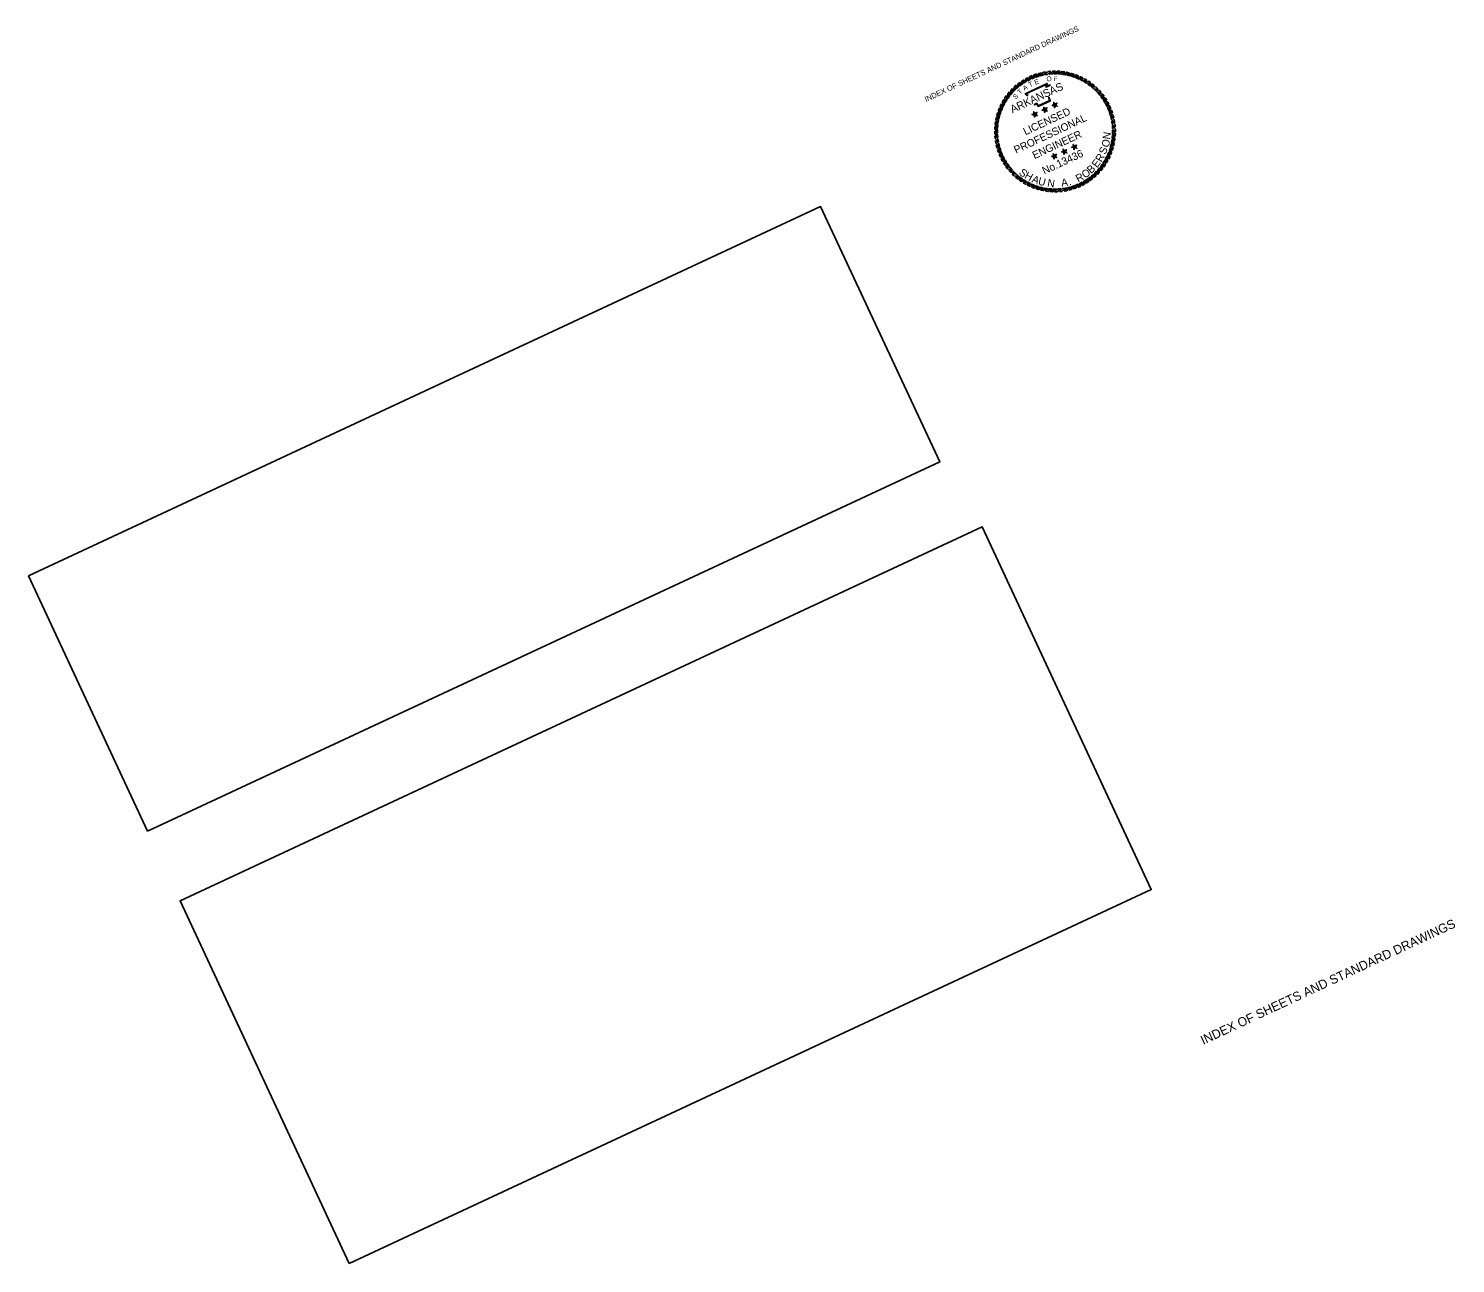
# Model space of a CAD drawing. Extents: x 757071 to 763666, y 1656563 to 1660766.
# Drawn here: x 757071 to 759892, y 1656563 to 1659005 of the extents above; entities that cross this region are included whole.
import ezdxf

# ---------------------------------------------------------------- set-up
doc = ezdxf.new("R2010")
doc.units = 0
for name, color, linetype in [('1', 7, 'Continuous'), ('60', 7, 'Continuous'), ('G-ANNO-SYMB', 7, 'Continuous')]:
    doc.layers.add(name, color=color, linetype=linetype)

msp = doc.modelspace()

# ---------------------------------------------------------------- linework, layer by layer
at = {"layer": '1'}
for points in [[(757306.4, 1657417.7), (758872.2, 1658147.8), (758636.7, 1658652.7), (757071, 1657922.6)], [(757704.8, 1656563.3), (759290.1, 1657302.5), (758955.7, 1658019.6), (757370.5, 1657280.3)]]:
    msp.add_lwpolyline(points, close=True, dxfattribs=at)
at = {"layer": 'G-ANNO-SYMB'}
for points in [[(759055.1, 1658911.6), (759050.4, 1658909.6), (759046.3, 1658901.5), (759051.2, 1658904)], [(759063.9, 1658914.8), (759059.1, 1658913.2), (759054.3, 1658905.4), (759059.4, 1658907.5)], [(759073, 1658917.3), (759068, 1658916), (759062.6, 1658908.7), (759067.9, 1658910.3)], [(759082.2, 1658919.1), (759077.1, 1658918.2), (759071.2, 1658911.3), (759076.6, 1658912.5)], [(759091.5, 1658920.1), (759086.4, 1658919.7), (759079.9, 1658913.2), (759085.4, 1658914)], [(759100.8, 1658920.4), (759095.7, 1658920.4), (759088.8, 1658914.4), (759094.3, 1658914.8)], [(759110.2, 1658920), (759105.1, 1658920.3), (759097.7, 1658915), (759103.2, 1658914.9)], [(759119.5, 1658918.9), (759114.4, 1658919.6), (759106.6, 1658914.8), (759112.2, 1658914.4)], [(759128.7, 1658917), (759123.7, 1658918.1), (759115.5, 1658913.9), (759121, 1658913.1)], [(759137.7, 1658914.4), (759132.8, 1658915.9), (759124.3, 1658912.4), (759129.7, 1658911.1)], [(759146.5, 1658911.1), (759141.7, 1658913), (759133, 1658910.1), (759138.2, 1658908.4)], [(759154.9, 1658907.1), (759150.3, 1658909.4), (759141.4, 1658907.2), (759146.5, 1658905.1)], [(759016.3, 1658886), (759012.7, 1658882.3), (759012, 1658873.2), (759015.6, 1658877.4)], [(759023.2, 1658892.3), (759019.3, 1658889), (759017.9, 1658879.9), (759021.8, 1658883.8)], [(759030.6, 1658898.1), (759026.5, 1658895), (759024.3, 1658886.1), (759028.6, 1658889.7)], [(759038.4, 1658903.3), (759034.1, 1658900.5), (759031.2, 1658891.8), (759035.7, 1658895.1)], [(759046.6, 1658907.8), (759042.1, 1658905.4), (759038.6, 1658896.9), (759043.3, 1658899.8)], [(759163.1, 1658902.5), (759158.7, 1658905.1), (759149.6, 1658903.6), (759154.6, 1658901.1)], [(759170.8, 1658897.2), (759166.6, 1658900.2), (759157.5, 1658899.4), (759162.2, 1658896.5)], [(759178.2, 1658891.4), (759174.2, 1658894.6), (759165.1, 1658894.6), (759169.5, 1658891.4)], [(759185, 1658885), (759181.3, 1658888.5), (759172.2, 1658889.3), (759176.4, 1658885.6)], [(759191.3, 1658878), (759187.9, 1658881.9), (759178.9, 1658883.3), (759182.8, 1658879.4)], [(758994.1, 1658856), (758991.9, 1658851.4), (758994, 1658842.5), (758996.1, 1658847.6)], [(758998.8, 1658864.1), (758996.1, 1658859.7), (758997.6, 1658850.7), (759000.1, 1658855.6)], [(759004, 1658871.9), (759001.1, 1658867.7), (759001.8, 1658858.6), (759004.7, 1658863.3)], [(759009.9, 1658879.2), (759006.6, 1658875.2), (759006.6, 1658866.1), (759009.9, 1658870.6)], [(759099.8, 1658853.4), (759098, 1658854.4), (759094.4, 1658852.7), (759098.3, 1658852)], [(759099.8, 1658853.4), (759100.2, 1658855.5), (759097.5, 1658858.4), (759098, 1658854.4)], [(759099.8, 1658853.4), (759098.3, 1658852), (759098.7, 1658848.1), (759100.7, 1658851.5)], [(759099.8, 1658853.4), (759101.9, 1658853.7), (759103.8, 1658857.1), (759100.2, 1658855.5)], [(759099.8, 1658853.4), (759100.7, 1658851.5), (759104.6, 1658850.8), (759101.9, 1658853.7)], [(759197.1, 1658870.6), (759194, 1658874.8), (759185.1, 1658876.9), (759188.7, 1658872.7)], [(759202.2, 1658862.8), (759199.5, 1658867.2), (759190.8, 1658870), (759194, 1658865.5)], [(759206.7, 1658854.6), (759204.3, 1658859.2), (759195.9, 1658862.7), (759198.8, 1658857.9)], [(759210.6, 1658846.1), (759208.6, 1658850.8), (759200.4, 1658855), (759202.9, 1658850)], [(758984.2, 1658829.7), (758983.1, 1658824.7), (758987.3, 1658816.6), (758988.2, 1658822)], [(758986.8, 1658838.7), (758985.3, 1658833.8), (758988.8, 1658825.4), (758990.1, 1658830.7)], [(758990.1, 1658847.5), (758988.3, 1658842.7), (758991.1, 1658834), (758992.8, 1658839.3)], [(759060.2, 1658835), (759058.4, 1658836), (759054.8, 1658834.3), (759058.7, 1658833.5)], [(759060.2, 1658835), (759060.6, 1658837), (759057.9, 1658839.9), (759058.4, 1658836)], [(759060.2, 1658835), (759058.7, 1658833.5), (759059.2, 1658829.6), (759061.1, 1658833.1)], [(759060.2, 1658835), (759062.3, 1658835.2), (759064.2, 1658838.7), (759060.6, 1658837)], [(759060.2, 1658835), (759061.1, 1658833.1), (759065, 1658832.3), (759062.3, 1658835.2)], [(759080, 1658844.2), (759078.2, 1658845.2), (759074.6, 1658843.5), (759078.5, 1658842.8)], [(759080, 1658844.2), (759080.4, 1658846.2), (759077.7, 1658849.1), (759078.2, 1658845.2)], [(759080, 1658844.2), (759078.5, 1658842.8), (759079, 1658838.8), (759080.9, 1658842.3)], [(759080, 1658844.2), (759082.1, 1658844.4), (759084, 1658847.9), (759080.4, 1658846.2)], [(759080, 1658844.2), (759080.9, 1658842.3), (759084.8, 1658841.5), (759082.1, 1658844.4)], [(759213.8, 1658837.3), (759212.1, 1658842.1), (759204.3, 1658846.9), (759206.5, 1658841.8)], [(759216.3, 1658828.2), (759215, 1658833.2), (759207.6, 1658838.6), (759209.3, 1658833.3)], [(759218.1, 1658819), (759217.2, 1658824.1), (759210.2, 1658830), (759211.5, 1658824.6)], [(758980.8, 1658801.9), (758980.9, 1658796.8), (758986.8, 1658789.8), (758986.4, 1658795.3)], [(758981.2, 1658811.2), (758980.9, 1658806.1), (758986.3, 1658798.7), (758986.3, 1658804.3)], [(758982.4, 1658820.5), (758981.6, 1658815.5), (758986.4, 1658807.7), (758986.9, 1658813.2)], [(759219.1, 1658809.7), (759218.6, 1658814.8), (759212.2, 1658821.3), (759213, 1658815.8)], [(759219.4, 1658800.4), (759219.3, 1658805.5), (759213.4, 1658812.5), (759213.8, 1658806.9)], [(759219, 1658791), (759219.3, 1658796.1), (759213.9, 1658803.5), (759213.9, 1658798)], [(758981.1, 1658792.5), (758981.6, 1658787.4), (758988, 1658780.9), (758987.2, 1658786.4)], [(758982.1, 1658783.2), (758983, 1658778.2), (758990, 1658772.2), (758988.7, 1658777.6)], [(758983.9, 1658774), (758985.2, 1658769), (758992.6, 1658763.7), (758990.9, 1658768.9)], [(759138.4, 1658770.6), (759136.6, 1658771.6), (759133, 1658769.9), (759136.9, 1658769.2)], [(759138.4, 1658770.6), (759138.8, 1658772.6), (759136.1, 1658775.5), (759136.6, 1658771.6)], [(759138.4, 1658770.6), (759136.9, 1658769.2), (759137.4, 1658765.3), (759139.3, 1658768.7)], [(759138.4, 1658770.6), (759140.5, 1658770.9), (759142.4, 1658774.3), (759138.8, 1658772.6)], [(759138.4, 1658770.6), (759139.3, 1658768.7), (759143.2, 1658768), (759140.5, 1658770.9)], [(759210, 1658754.8), (759211.9, 1658759.5), (759209.1, 1658768.2), (759207.4, 1658763)], [(759213.3, 1658763.5), (759214.8, 1658768.4), (759211.3, 1658776.9), (759210, 1658771.5)], [(759215.9, 1658772.5), (759217.1, 1658777.5), (759212.9, 1658785.7), (759212, 1658780.2)], [(759217.8, 1658781.7), (759218.5, 1658786.8), (759213.8, 1658794.6), (759213.3, 1658789.1)], [(758986.4, 1658765), (758988, 1658760.1), (758995.8, 1658755.3), (758993.7, 1658760.5)], [(758989.6, 1658756.2), (758991.6, 1658751.5), (758999.8, 1658747.3), (758997.3, 1658752.2)], [(758993.4, 1658747.6), (758995.8, 1658743.1), (759004.3, 1658739.6), (759001.4, 1658744.3)], [(759098.9, 1658752.2), (759097, 1658753.2), (759093.4, 1658751.5), (759097.3, 1658750.7)], [(759098.9, 1658752.2), (759099.2, 1658754.2), (759096.5, 1658757.1), (759097, 1658753.2)], [(759098.9, 1658752.2), (759097.3, 1658750.7), (759097.8, 1658746.8), (759099.7, 1658750.3)], [(759098.9, 1658752.2), (759100.9, 1658752.4), (759102.8, 1658755.9), (759099.2, 1658754.2)], [(759098.9, 1658752.2), (759099.7, 1658750.3), (759103.6, 1658749.5), (759100.9, 1658752.4)], [(759118.6, 1658761.4), (759116.8, 1658762.4), (759113.2, 1658760.7), (759117.1, 1658760)], [(759118.6, 1658761.4), (759119, 1658763.4), (759116.3, 1658766.3), (759116.8, 1658762.4)], [(759118.6, 1658761.4), (759117.1, 1658760), (759117.6, 1658756), (759119.5, 1658759.5)], [(759118.6, 1658761.4), (759120.7, 1658761.6), (759122.6, 1658765.1), (759119, 1658763.4)], [(759118.6, 1658761.4), (759119.5, 1658759.5), (759123.4, 1658758.7), (759120.7, 1658761.6)], [(759196.2, 1658730.4), (759199.1, 1658734.6), (759198.4, 1658743.7), (759195.5, 1658739)], [(759201.4, 1658738.1), (759204, 1658742.6), (759202.6, 1658751.6), (759200.1, 1658746.7)], [(759206.1, 1658746.3), (759208.3, 1658750.9), (759206.2, 1658759.8), (759204, 1658754.7)], [(758998, 1658739.4), (759000.7, 1658735.1), (759009.4, 1658732.3), (759006.2, 1658736.8)], [(759003.1, 1658731.6), (759006.2, 1658727.5), (759015.1, 1658725.4), (759011.5, 1658729.6)], [(759008.9, 1658724.2), (759012.3, 1658720.4), (759021.3, 1658718.9), (759017.4, 1658722.9)], [(759015.2, 1658717.3), (759018.9, 1658713.7), (759028, 1658713), (759023.8, 1658716.6)], [(759169.6, 1658704.2), (759173.7, 1658707.2), (759175.9, 1658716.1), (759171.6, 1658712.5)], [(759177, 1658709.9), (759180.9, 1658713.3), (759182.3, 1658722.3), (759178.4, 1658718.4)], [(759183.9, 1658716.2), (759187.5, 1658719.9), (759188.2, 1658729), (759184.6, 1658724.8)], [(759190.3, 1658723.1), (759193.6, 1658727), (759193.6, 1658736.2), (759190.3, 1658731.7)], [(759022, 1658710.9), (759026, 1658707.6), (759035.1, 1658707.6), (759030.7, 1658710.9)], [(759029.4, 1658705), (759033.5, 1658702.1), (759042.7, 1658702.8), (759037.9, 1658705.7)], [(759037.1, 1658699.8), (759041.5, 1658697.2), (759050.6, 1658698.6), (759045.6, 1658701.1)], [(759045.3, 1658695.2), (759049.9, 1658692.9), (759058.8, 1658695), (759053.6, 1658697.2)], [(759053.7, 1658691.2), (759058.5, 1658689.3), (759067.2, 1658692.1), (759061.9, 1658693.8)], [(759062.5, 1658687.9), (759067.4, 1658686.4), (759075.9, 1658689.9), (759070.5, 1658691.2)], [(759071.5, 1658685.3), (759076.5, 1658684.2), (759084.7, 1658688.3), (759079.2, 1658689.2)], [(759080.7, 1658683.4), (759085.8, 1658682.7), (759093.6, 1658687.4), (759088, 1658687.9)], [(759090, 1658682.2), (759095.1, 1658681.9), (759102.5, 1658687.3), (759097, 1658687.3)], [(759099.3, 1658681.8), (759104.5, 1658681.9), (759111.4, 1658687.8), (759105.9, 1658687.4)], [(759108.7, 1658682.1), (759113.8, 1658682.6), (759120.3, 1658689.1), (759114.8, 1658688.2)], [(759118, 1658683.2), (759123.1, 1658684), (759129, 1658691), (759123.6, 1658689.7)], [(759127.2, 1658684.9), (759132.2, 1658686.2), (759137.6, 1658693.6), (759132.3, 1658691.9)], [(759136.2, 1658687.4), (759141.1, 1658689.1), (759145.9, 1658696.9), (759140.8, 1658694.8)], [(759145.1, 1658690.6), (759149.8, 1658692.6), (759153.9, 1658700.8), (759149, 1658698.3)], [(759153.6, 1658694.5), (759158.1, 1658696.9), (759161.6, 1658705.3), (759156.9, 1658702.4)], [(759161.8, 1658699), (759166.1, 1658701.7), (759169, 1658710.4), (759164.5, 1658707.2)]]:
    msp.add_lwpolyline(points, close=True, dxfattribs=at)
for points in [[(759046.2, 1658871.5), (759041.1, 1658875.8), (759084.7, 1658896.2), (759083.2, 1658889.9), (759086.1, 1658891.3), (759088.6, 1658892.5), (759091.2, 1658893.4)], [(759046.7, 1658872.1), (759042.5, 1658875.6), (759083.6, 1658894.8), (759082.1, 1658888.5), (759086.5, 1658890.6), (759088.9, 1658891.8), (759091.4, 1658892.7)], [(759088.9, 1658869.2), (759088.5, 1658868.3), (759088.6, 1658867.2), (759089.4, 1658864.9), (759090.8, 1658861.9), (759066.5, 1658850.5), (759064.6, 1658854.6), (759064.2, 1658855.5), (759063, 1658855.3), (759059.6, 1658853.7), (759058.5, 1658854.3)], [(759088.2, 1658869.5), (759087.7, 1658868.4), (759087.9, 1658867.1), (759088.7, 1658864.6), (759089.8, 1658862.2), (759066.9, 1658851.5), (759065.3, 1658854.9), (759064.6, 1658856.3), (759062.8, 1658856.1), (759059.6, 1658854.6), (759058.9, 1658855)]]:
    msp.add_lwpolyline(points, dxfattribs=at)

# ---------------------------------------------------------------- texts
at = {"layer": '1'}
msp.add_text('INDEX OF SHEETS AND STANDARD DRAWINGS', height=10.552, rotation=25, dxfattribs=at).set_placement((758845.2, 1658859.3))
at = {"layer": '60'}
msp.add_text('INDEX OF SHEETS AND STANDARD DRAWINGS', height=18, rotation=25, dxfattribs=at).set_placement((759393, 1656995.3))
at = {"layer": 'G-ANNO-SYMB'}
for s, height, rotation, p in [('O', 9.49, 6.2218, (759083.7, 1658900)), ('F', 9.49, 0.3628, (759097.4, 1658900.8)), ('ARKANSAS', 15.49, 25, (759015.8, 1658837)), ('T', 9.49, 41.9015, (759030.8, 1658873.8)), ('A', 9.49, 33.6788, (759039.9, 1658881.4)), ('T', 9.49, 26.4789, (759050.3, 1658888.3)), ('E', 9.49, 21.672, (759061.4, 1658893.2)), ('S', 9.49, 44.7726, (759022.1, 1658863.8)), ('PROFESSIONAL', 15, 25, (759023, 1658756.9)), ('LICENSED', 15, 25, (759041.5, 1658793.2)), ('ENGINEER', 15, 25, (759059.5, 1658746.2)), ('N', 15, 81.1007, (759208.7, 1658784.6)), ('S', 15, 68.4878, (759199.9, 1658754.6)), ('O', 15, 69.7757, (759205, 1658768)), ('No.13436', 14.94, 25, (759078.9, 1658715.8)), ('E', 15, 52.8315, (759183, 1658728.2)), ('R', 15, 60.6597, (759191.7, 1658739.5)), ('S', 15, 323.1636, (759027.3, 1658717.3)), ('H', 15, 330.619, (759038.5, 1658709.6)), ('A', 15, 338.4472, (759052.9, 1658701.2)), ('R', 15, 28.2287, (759145.8, 1658700.2)), ('O', 15, 36.4296, (759159.3, 1658707.6)), ('B', 15, 43.885, (759171.5, 1658716.8)), ('U', 15, 345.9026, (759065.5, 1658696.3)), ('N', 15, 349.9326, (759083.9, 1658692.5)), ('A', 15, 8.0991, (759113.1, 1658691.9)), ('.', 15, 16.3, (759128.3, 1658694.2))]:
    msp.add_text(s, height=height, rotation=rotation, dxfattribs=at).set_placement(p)

doc.saveas('drawing.dxf')
